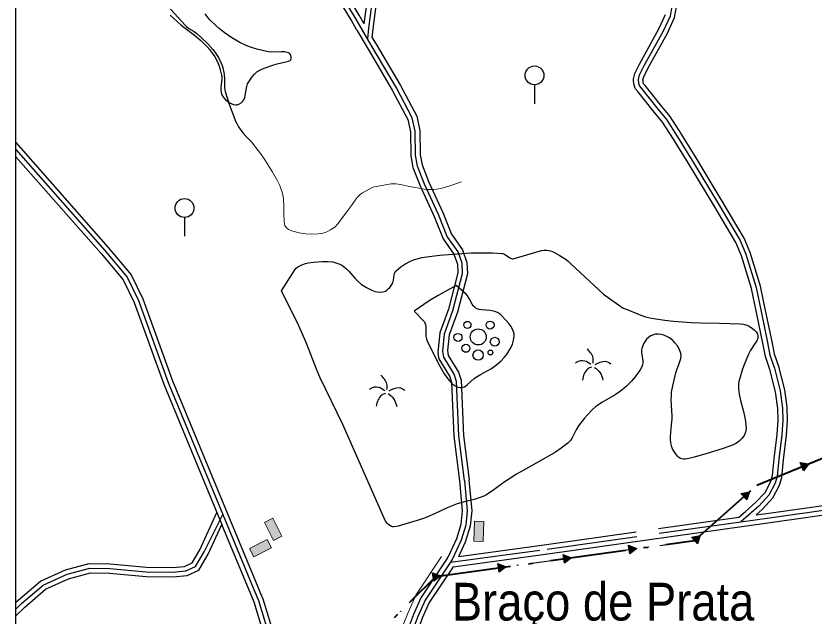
# Model space of a CAD drawing. Extents: x -64005 to -55000, y -89025 to -80000.
# Drawn here: x -64000 to -62306, y -86993 to -85720 of the extents above; entities that cross this region are included whole.
import ezdxf
from ezdxf.enums import TextEntityAlignment as Align

# ---------------------------------------------------------------- set-up
doc = ezdxf.new("R2010")
doc.units = 0
doc.header["$LTSCALE"] = 32
for name, pattern in [('DASH_DOUBLE_DOT', [9.2, 5, -1.2, 0.3, -1.2, 0.3, -1.2]), ('DOT_DASHED', [7.7, 5, -1.2, 0.3, -1.2]), ('LONG_DASHED', [7.5, 6, -1.5])]:
    doc.linetypes.add(name, pattern=pattern)
for name, color, linetype, lineweight in [('18', 7, 'Continuous', 25), ('2', 7, 'Continuous', 25), ('24', 7, 'Continuous', 25), ('32', 7, 'Continuous', 25), ('33', 7, 'Continuous', 25), ('34', 7, 'Continuous', 25), ('39', 7, 'LONG_DASHED', 25), ('6', 7, 'Continuous', 25), ('63', 7, 'DASH_DOUBLE_DOT', 25), ('7', 7, 'Continuous', 13), ('8', 7, 'Continuous', 25)]:
    doc.layers.add(name, color=color, linetype=linetype, lineweight=lineweight)
doc.layers.add('45', color=7, linetype='Continuous')

msp = doc.modelspace()

# ---------------------------------------------------------------- hatches: boundary and pattern name
at = {"layer": '18'}
for points in [[(-62335.55, -86667.32), (-62317.22, -86669.79), (-62328.52, -86684.43)], [(-62461.12, -86732.67), (-62443, -86728.94), (-62448.82, -86746.5)], [(-62565.74, -86825.7), (-62547.62, -86821.96), (-62553.45, -86839.52)], [(-62699.56, -86842.72), (-62682.41, -86849.67), (-62697, -86861.04)], [(-62838.22, -86862.05), (-62821.07, -86869), (-62835.66, -86880.37)], [(-62976.88, -86881.37), (-62959.73, -86888.32), (-62974.32, -86899.7)], [(-63115.54, -86900.7), (-63098.39, -86907.65), (-63112.98, -86919.02)]]:
    msp.add_hatch(color=256, dxfattribs=at).paths.add_polyline_path(points)
at = {"layer": '7'}
for points in [[(-63435.3, -86823.22), (-63454.7, -86785.41), (-63472.5, -86794.54), (-63453.1, -86832.35)], [(-63008.3, -86834.71), (-63006.89, -86792.23), (-63026.88, -86791.57), (-63028.29, -86834.05)], [(-63495.3, -86867.24), (-63457.47, -86847.86), (-63466.58, -86830.06), (-63504.41, -86849.44)]]:
    msp.add_hatch(color=256, dxfattribs=at).paths.add_polyline_path(points)

# ---------------------------------------------------------------- linework, layer by layer
at = {"layer": '18'}
for p, q in [((-62400.47, -86703.99), (-62332.03, -86675.88)), ((-62510.26, -86788.74), (-62454.97, -86739.59)), ((-62632.89, -86842.77), (-62559.62, -86832.55)), ((-62771.55, -86862.09), (-62698.28, -86851.88)), ((-62910.21, -86881.42), (-62836.94, -86871.21)), ((-63048.87, -86900.75), (-62975.6, -86890.54)), ((-63165.4, -86965), (-63112.65, -86913.14))]:
    msp.add_line(p, q, dxfattribs=at)
at = {"layer": '18', "linetype": 'DOT_DASHED', "lineweight": 40}
msp.add_lwpolyline([(-64000, -87327.84), (-63934.19, -87335.68), (-63775.91, -87352.69), (-63696.16, -87339.73), (-63513.74, -87307.46), (-63108.5, -86909.06), (-62559.52, -86832.54), (-62427.35, -86715.03), (-61987.81, -86534.48)], dxfattribs=at)
at = {"layer": '18'}
for points in [[(-62335.55, -86667.32), (-62317.22, -86669.79), (-62328.52, -86684.43)], [(-62461.12, -86732.67), (-62443, -86728.94), (-62448.82, -86746.5)], [(-62565.74, -86825.7), (-62547.62, -86821.96), (-62553.45, -86839.52)], [(-62699.56, -86842.72), (-62682.41, -86849.67), (-62697, -86861.04)], [(-62838.22, -86862.05), (-62821.07, -86869), (-62835.66, -86880.37)], [(-62976.88, -86881.37), (-62959.73, -86888.32), (-62974.32, -86899.7)], [(-63115.54, -86900.7), (-63098.39, -86907.65), (-63112.98, -86919.02)]]:
    msp.add_lwpolyline(points, close=True, dxfattribs=at)
for centre in [(-62423.59, -86713.49), (-62528.94, -86805.35), (-62657.66, -86846.22), (-62796.31, -86865.54), (-62934.97, -86884.87), (-63073.63, -86904.2), (-63183.23, -86982.53)]:
    msp.add_circle(centre, 0.5, dxfattribs=at)
at = {"layer": '2'}
msp.add_lwpolyline([(-63671.62, -85705.77), (-63640.29, -85740), (-63637.94, -85742.29), (-63632.72, -85746.26), (-63621.42, -85753.24), (-63616.07, -85757.12), (-63608.04, -85764.11), (-63592.74, -85778.99), (-63581.84, -85791.28), (-63576.86, -85797.78), (-63569.95, -85808.23), (-63564.84, -85818.32), (-63562.25, -85825.27), (-63560.82, -85829.99), (-63558.56, -85839.62), (-63557.89, -85844.11), (-63557.49, -85853.21), (-63557.58, -85865.4), (-63557.3, -85871.43), (-63556.44, -85877.36), (-63555.71, -85880.28), (-63546.44, -85909.31), (-63537.87, -85933.33), (-63533.71, -85943.11), (-63531.34, -85947.87), (-63527.43, -85954.82), (-63520.76, -85964.81), (-63518.01, -85968.31), (-63512.03, -85974.86), (-63499.54, -85987.41)], dxfattribs=at)
at = {"layer": '2', "lineweight": 13}
msp.add_lwpolyline([(-63054.23, -86071.49), (-63081.28, -86080.78), (-63095.12, -86084.86), (-63102.22, -86086.39), (-63112.96, -86087.88), (-63123.68, -86088.23), (-63128.99, -86087.91), (-63136.9, -86086.86), (-63152.71, -86083.7), (-63164.59, -86081.51), (-63171, -86080.39), (-63183.9, -86077.69), (-63193.59, -86076.17), (-63203.23, -86075.92), (-63208.02, -86076.52), (-63242.68, -86082.95), (-63264.05, -86095.08), (-63268.31, -86097.92), (-63270.91, -86100.1), (-63275.65, -86105.03), (-63279.93, -86110.52), (-63287.84, -86122.23), (-63293.95, -86130.75), (-63316.73, -86160.71), (-63323.42, -86167.62), (-63328.46, -86171.53), (-63332.11, -86173.84), (-63340.1, -86177.83), (-63343.73, -86179.22), (-63351.01, -86181.19), (-63358.29, -86182.3), (-63372.85, -86182.82), (-63384.46, -86182.24), (-63390.27, -86181.57), (-63398.97, -86180.04), (-63412.02, -86176.41), (-63421.28, -86172.67), (-63425.26, -86169.99), (-63428.19, -86166.46), (-63429.11, -86164.29), (-63430.73, -86155.89), (-63431.05, -86139.03), (-63431.05, -86122.46), (-63432.15, -86109.54), (-63433.12, -86103.12), (-63435.24, -86093.61), (-63438.27, -86084.26), (-63440.16, -86079.67), (-63445.1, -86069.38), (-63456.17, -86049.85), (-63471.75, -86024.8), (-63478.85, -86014.39), (-63497.99, -85989.43), (-63499.54, -85987.41)], dxfattribs=at)
at = {"layer": '24'}
for points in [[(-63972.31, -87227.87), (-63975.53, -87229.32), (-64000, -87237.1), (-64000, -85340.91)], [(-63672.91, -85718.52), (-63657.12, -85732.6), (-63648.98, -85739.3), (-63621.27, -85760.7), (-63607.76, -85772.28), (-63594.26, -85785.22), (-63588.51, -85791.69), (-63583.27, -85798.56), (-63577.95, -85806.69), (-63572.33, -85817.04), (-63569.54, -85824.08), (-63567.39, -85831.23), (-63563.97, -85845.71), (-63563.33, -85850.22), (-63563.26, -85853.26), (-63565.14, -85871.86), (-63565.23, -85876.01), (-63564.47, -85882.18), (-63562.71, -85887.27), (-63559.43, -85892.76), (-63554.39, -85898.38), (-63550.55, -85901.52), (-63546.48, -85904.19), (-63538.15, -85908.05), (-63534.01, -85908.71), (-63531.02, -85908.44), (-63526.98, -85907.25), (-63522.26, -85904.55), (-63518.19, -85900.39), (-63516.4, -85897.6), (-63514.28, -85892.69), (-63513.17, -85888.59), (-63510.17, -85869.88), (-63508.17, -85864.12), (-63498.52, -85849.09), (-63493.86, -85843.35), (-63488.39, -85838.36), (-63482.47, -85834.66), (-63476.79, -85831.95), (-63471.04, -85829.66), (-63454.99, -85824.07), (-63445.82, -85821.71), (-63427.32, -85817.57), (-63421.38, -85815.84), (-63417.95, -85814.55), (-63416.38, -85812.69), (-63415.75, -85809.89), (-63415.79, -85807.73), (-63416.85, -85803.29), (-63418.39, -85800.39)], [(-63418.39, -85800.39), (-63419.72, -85798.91), (-63421.65, -85797.82), (-63430.05, -85796.3), (-63436.9, -85796.05), (-63457.57, -85796.57), (-63464.31, -85795.96), (-63467.62, -85795.31), (-63489.04, -85790.05), (-63499.7, -85786.93), (-63510.25, -85783.11), (-63524.68, -85776.36), (-63542.07, -85766.42), (-63558.31, -85755.12), (-63568.65, -85746.76), (-63575.37, -85740.81), (-63588.52, -85727.95), (-63592.16, -85723.99), (-63598.7, -85715.79)], [(-63305.96, -86586.27), (-63354.8, -86486.09), (-63362.27, -86468.84), (-63382.75, -86416.19), (-63393.64, -86390.17), (-63399.67, -86377.43), (-63436.68, -86303.06), (-63408.14, -86258.62), (-63405.08, -86255.2), (-63401.54, -86252.28), (-63397.14, -86249.59), (-63393.31, -86247.8), (-63385.56, -86245.21), (-63378.96, -86243.74), (-63368.76, -86242.28), (-63349.01, -86240.68), (-63338.26, -86240.46), (-63327.37, -86241.68), (-63316.66, -86244.69), (-63312.74, -86246.35), (-63308.29, -86248.72), (-63305.52, -86250.51), (-63297.96, -86256.69), (-63293.38, -86261.33), (-63280.5, -86276.14), (-63273.76, -86283.22), (-63266.25, -86289.45), (-63255.83, -86295.87), (-63244.57, -86301.49), (-63237.65, -86304.01), (-63234.2, -86304.91), (-63227.43, -86305.86), (-63220.94, -86305.42), (-63215.71, -86303.56), (-63212.94, -86301.75), (-63209.05, -86298.25), (-63206.61, -86295.56), (-63202.06, -86289.78), (-63200.14, -86286.33), (-63199.2, -86283.35), (-63198.64, -86280.24), (-63197.46, -86269.21), (-63196.72, -86266.27), (-63195.15, -86262.89), (-63192.89, -86260.22), (-63187, -86255.23), (-63182.97, -86252.15), (-63174.68, -86246.6), (-63162.17, -86240.01), (-63154.18, -86236.8), (-63148.05, -86234.81), (-63138.62, -86232.52), (-63122.74, -86230.1), (-63100.57, -86227.39), (-63063.61, -86224.13), (-63034, -86222.51), (-63012.26, -86222.05), (-62988.07, -86222.49), (-62968.82, -86223.52), (-62966.8, -86223.85), (-62962.92, -86225.48), (-62951.86, -86233.07), (-62948.16, -86234.69), (-62946.26, -86235.02), (-62944.33, -86234.94), (-62884.28, -86217.39), (-62879.04, -86216.39), (-62873.23, -86216.41), (-62868.59, -86217.17), (-62865.12, -86218.11), (-62858.18, -86220.8), (-62846.65, -86226.98), (-62833.88, -86235.06), (-62827.65, -86240.19), (-62822.3, -86245.77), (-62752.81, -86310.19), (-62711.09, -86339.75)], [(-62711.09, -86339.75), (-62702.54, -86342.74), (-62673.52, -86354.61), (-62663.67, -86357.97), (-62651.04, -86361.02), (-62641.69, -86362.57), (-62622.95, -86365.23), (-62604.17, -86367.33), (-62566.49, -86370.17), (-62546.58, -86370.95), (-62506.74, -86371.51), (-62462.76, -86372.82), (-62455.77, -86373.8), (-62448.78, -86375.78), (-62445.29, -86377.28), (-62439.21, -86380.7), (-62436.26, -86382.75), (-62432.18, -86386.14), (-62428.75, -86389.84), (-62425.94, -86394.39), (-62424.94, -86397.72), (-62424.91, -86400.71), (-62425.48, -86403.38), (-62427.59, -86408.72), (-62430.67, -86414.05), (-62441.72, -86430.35), (-62445.29, -86437.4), (-62454.8, -86461.43), (-62459.22, -86473.65), (-62463.03, -86486.09), (-62465.24, -86495.33), (-62466.07, -86501.22), (-62466.36, -86511.1), (-62465.11, -86522.25), (-62462.01, -86535.56), (-62455.57, -86558.75), (-62452.1, -86575.12), (-62450.42, -86586.69), (-62450.32, -86595.34), (-62451.39, -86602.45), (-62452.74, -86606.58), (-62454.94, -86610.91), (-62459.06, -86616.47), (-62463.39, -86620.7), (-62468.25, -86624.4), (-62471.7, -86626.54), (-62478.89, -86629.96), (-62498.48, -86637.04), (-62537.97, -86649.33), (-62560.37, -86655.66), (-62571.58, -86658.51), (-62578.92, -86659.81), (-62582.67, -86659.87), (-62586.38, -86659.34), (-62590.62, -86657.73), (-62593.52, -86655.79), (-62596.03, -86653.41), (-62600.27, -86648.19), (-62604.24, -86641.92), (-62606.28, -86637.73), (-62607.88, -86633.53), (-62609.91, -86625.11), (-62610.63, -86618.08), (-62610.7, -86612.45), (-62610.2, -86603.98), (-62608.22, -86586.99), (-62607.2, -86574.23)], [(-62607.2, -86574.23), (-62607.23, -86567.84), (-62608.94, -86534.51), (-62608.71, -86523.42), (-62608.25, -86517.9), (-62605.97, -86504.14), (-62599.08, -86477.15), (-62597, -86470.33), (-62591.97, -86456.76), (-62588.9, -86446.59), (-62588.28, -86440.32), (-62588.85, -86435.33), (-62591.32, -86427.85), (-62593.93, -86422.89), (-62596.06, -86419.58), (-62601.12, -86412.97), (-62604.15, -86409.65), (-62606.22, -86407.67), (-62612.58, -86402.81), (-62616.97, -86400.34), (-62624.48, -86397.32), (-62630.66, -86395.66), (-62635.78, -86394.93), (-62642.47, -86395.2), (-62646.53, -86396.08), (-62652.47, -86398.56), (-62654.37, -86399.71), (-62657.14, -86401.77), (-62661.21, -86405.68), (-62663.85, -86408.95), (-62666.99, -86414.09), (-62668.67, -86417.67), (-62671.4, -86425.22), (-62672.06, -86428.01), (-62672.28, -86433.76), (-62669.53, -86451.47), (-62669.35, -86455.31), (-62669.9, -86459.95), (-62671.4, -86463.93), (-62675.06, -86470.38), (-62677.67, -86474.53), (-62686.28, -86486.33), (-62692.63, -86493.71), (-62699.41, -86500.72), (-62704.16, -86505.23), (-62714.17, -86513.86), (-62718.62, -86517.29), (-62727.88, -86523.48), (-62756.59, -86539.95), (-62765.73, -86545.93), (-62770.1, -86549.21), (-62776.31, -86554.62), (-62786.83, -86565.61), (-62793.39, -86573.32), (-62805.85, -86589.27), (-62810.86, -86597.45), (-62819.36, -86614.91), (-62822.8, -86620.23), (-62824.8, -86622.66), (-62828.25, -86625.95), (-62842.69, -86636.85), (-62854.65, -86644.88), (-62873.1, -86656.07), (-62929.65, -86687.37), (-62938.91, -86692.81), (-62952.52, -86701.36), (-62963.55, -86709.08), (-62985.3, -86725.15), (-62992.76, -86730.21), (-63002.44, -86736), (-63007.18, -86738.39), (-63016.99, -86742.3), (-63027.14, -86745.38), (-63047.86, -86750.45), (-63063.22, -86754.71), (-63070.67, -86757.41), (-63084.5, -86763.4), (-63111.88, -86776.2), (-63132.81, -86784.93), (-63148.3, -86790.12), (-63188.7, -86801.9), (-63193.26, -86802.92), (-63197.79, -86803.35), (-63200.02, -86803.27), (-63204.45, -86802), (-63209.21, -86798.63), (-63212.02, -86795.59), (-63215.95, -86789.75), (-63218.37, -86784.94), (-63305.96, -86586.27)]]:
    msp.add_lwpolyline(points, dxfattribs=at)
msp.add_lwpolyline([(-63065.82, -86291.3), (-63104.09, -86312.94), (-63122.95, -86324.2), (-63155.01, -86345.83), (-63134.97, -86366.49), (-63133.01, -86368.96), (-63132.03, -86370.74), (-63130.7, -86374.58), (-63129.92, -86380.91), (-63130.07, -86394.65), (-63129.85, -86399.28), (-63128.85, -86404.92), (-63127.71, -86408.16), (-63100.49, -86462.49), (-63092.02, -86477.24), (-63085.72, -86486.64), (-63079.85, -86494), (-63074.47, -86499.44), (-63071.71, -86501.73), (-63067.5, -86504.54), (-63063.19, -86506.57), (-63058.03, -86507.83), (-63054.25, -86507.95), (-63050.79, -86507.46), (-63047.65, -86506.3), (-63045.12, -86504.79), (-63041.3, -86501.79), (-63027.69, -86489.03), (-63024.73, -86486.78), (-63013.68, -86480.05), (-62990.66, -86467.39), (-62979.21, -86459.54), (-62970.09, -86451.47), (-62963.47, -86444.35), (-62958.94, -86438.72), (-62954.84, -86432.9), (-62949.64, -86423.95), (-62946.29, -86416.4), (-62943.6, -86407.41), (-62942.86, -86403), (-62942.55, -86398.67), (-62942.67, -86394.89), (-62943.21, -86391.57), (-62944.97, -86386.08), (-62949.01, -86378.46), (-62953.66, -86372.02), (-62959.14, -86365.67), (-62971.62, -86353.32), (-62975.43, -86350.35), (-62978.12, -86348.81), (-62983.8, -86346.61), (-62989.76, -86345.32), (-62993.83, -86344.81), (-63010.93, -86343.54), (-63016.52, -86342.53), (-63019.15, -86341.75), (-63022.86, -86340.13), (-63026.21, -86337.84), (-63029.17, -86334.77), (-63031.65, -86331.12), (-63037.81, -86319.01), (-63041.48, -86313.43), (-63043.77, -86311.04)], close=True, dxfattribs=at)
at = {"layer": '32'}
for p, q in [((-62899.32, -85866), (-62899.32, -85906)), ((-63642.15, -86147.31), (-63642.15, -86187.31))]:
    msp.add_line(p, q, dxfattribs=at)
for centre in [(-62899.32, -85846), (-63642.15, -86127.31)]:
    msp.add_circle(centre, 20, dxfattribs=at)
at = {"layer": '33'}
for points in [[(-62775.01, -86456.15), (-62775.01, -86445.31), (-62780.35, -86434.17), (-62787.59, -86426.47)], [(-62779.54, -86459.24), (-62792.74, -86451.82), (-62810.52, -86455.22), (-62812.22, -86456.54)], [(-62778.26, -86464.67), (-62785.98, -86468.39), (-62794, -86478.95), (-62797.64, -86492.07)], [(-62772.06, -86465.21), (-62760.12, -86476.83), (-62754.14, -86492.75)], [(-62770.27, -86459.21), (-62749.29, -86452.39), (-62737.19, -86457.65)], [(-63212.58, -86511.99), (-63212.58, -86501.15), (-63217.92, -86490.01), (-63225.16, -86482.31)], [(-63217.11, -86515.08), (-63230.31, -86507.66), (-63248.09, -86511.06), (-63249.79, -86512.38)], [(-63207.84, -86515.05), (-63186.86, -86508.23), (-63174.76, -86513.49)], [(-63215.83, -86520.51), (-63223.55, -86524.23), (-63231.57, -86534.79), (-63235.21, -86547.91)], [(-63209.63, -86521.05), (-63197.69, -86532.67), (-63191.71, -86548.59)]]:
    msp.add_spline(points, degree=3, dxfattribs=at)
at = {"layer": '34'}
for centre, radius in [((-63041.69, -86375.15), 7.5), ((-62993.69, -86375.62), 8.5), ((-63061.71, -86401.66), 8.5), ((-63018.72, -86400.8), 17), ((-62983.56, -86411.04), 9.5), ((-63044.83, -86424.85), 8.5), ((-63018.97, -86439.23), 11), ((-62992.84, -86433.75), 5)]:
    msp.add_circle(centre, radius, dxfattribs=at)
at = {"layer": '39', "linetype": 'Continuous'}
msp.add_line((-63560.89, -86777.29), (-63494.9, -86936.48), dxfattribs=at)
at = {"layer": '39'}
for points in [[(-63253.9, -85768.32), (-63280.08, -85723.39), (-63339.56, -85625.07), (-63389.57, -85575.91), (-63480.62, -85489.18), (-63583.07, -85394.9)], [(-63244.55, -85691.89), (-63251.71, -85746.02), (-63253.9, -85768.32)], [(-62607.87, -85699.34), (-62611.44, -85720.05), (-62626.08, -85752.08), (-62667.76, -85826.92), (-62676.87, -85845.71), (-62679.08, -85854.54), (-62678.53, -85862.27), (-62676.6, -85868.62), (-62672.18, -85873.87), (-62639.33, -85914.73), (-62619.17, -85939.3), (-62595.98, -85976.01), (-62564.79, -86026.26), (-62509.57, -86117.64), (-62462.9, -86196.04), (-62450.76, -86225.31), (-62428.94, -86295.71), (-62418.45, -86346.8), (-62404.93, -86412.23), (-62399.4, -86439.57), (-62390.01, -86466.62), (-62377.86, -86514.94), (-62372.61, -86551.66), (-62372.33, -86577.34), (-62374.54, -86608.26), (-62380.35, -86660.17), (-62383.94, -86696.62), (-62388.36, -86710.98), (-62401.61, -86736.38), (-62422.87, -86759.31), (-62444.68, -86778.63), (-62461.36, -86792.73)], [(-63047.64, -86705.11), (-63059.65, -86610.54), (-63064.82, -86494.96), (-63069.59, -86479.45), (-63091.93, -86443.41), (-63094.05, -86431.26), (-63090.61, -86394.18), (-63072.5, -86345.01), (-63051.88, -86266.13), (-63052.74, -86244.56), (-63061.36, -86220.41), (-63084.63, -86187.65), (-63102.76, -86141.06), (-63132.93, -86076.39), (-63147.58, -86038.44), (-63151.85, -86015.43), (-63152.72, -85964.55), (-63158.75, -85936.09), (-63192.37, -85872.27), (-63244.09, -85785.16), (-63253.9, -85768.32)], [(-62461.36, -86792.73), (-62400.43, -86784.16), (-62105.63, -86742.73), (-61796.63, -86698.55)], [(-63047.64, -86705.11), (-63041.95, -86769.54), (-63045.25, -86799.68), (-63054.9, -86831.71), (-63073.26, -86871.04), (-63077.84, -86878.72)], [(-64000, -86978.32), (-63988.13, -86966.25), (-63942.44, -86927.45), (-63891.57, -86904.17), (-63843.28, -86891.23), (-63801.03, -86892.08), (-63723.44, -86898.97), (-63667.39, -86899.82), (-63639.38, -86897.14), (-63618.68, -86887.65), (-63600.58, -86856.59), (-63560.89, -86777.29)], [(-63077.84, -86878.72), (-62872.34, -86850.53), (-62461.36, -86792.73)], [(-63077.84, -86878.72), (-63131.49, -86959.16), (-63146.78, -86993.57), (-63157.5, -87021.62)]]:
    msp.add_lwpolyline(points, dxfattribs=at)
at = {"layer": '39', "linetype": 'Continuous'}
for points in [[(-64000, -86003.46), (-63811.7, -86217.23), (-63763.78, -86274.14), (-63739.82, -86323.58), (-63676.93, -86497.37), (-63560.89, -86777.29)], [(-63494.9, -86936.48), (-63485.26, -86959.74), (-63458.91, -87046.23)]]:
    msp.add_lwpolyline(points, dxfattribs=at)
at = {"layer": '6'}
for points in [[(-64000, -85988.33), (-63804.12, -86210.69), (-63755.33, -86268.66), (-63730.59, -86319.69), (-63667.6, -86493.75), (-63488.63, -86925.51), (-63480.72, -86944.59)], [(-64000, -86018.58), (-63819.28, -86223.76), (-63772.23, -86279.63), (-63749.05, -86327.48), (-63686.26, -86500.99), (-63573.41, -86773.2), (-63562.96, -86798.41)], [(-63318.01, -87510.1), (-63350.89, -87470.08), (-63375.98, -87426), (-63406.05, -87375.63), (-63423.29, -87341.93), (-63430.55, -87306.47), (-63429.02, -87264.9), (-63428.29, -87233.1), (-63438.17, -87182.82), (-63457.54, -87085.03), (-63494.68, -86963.12), (-63562.96, -86798.41)], [(-63480.72, -86944.59), (-63475.84, -86956.36), (-63451.26, -87037.02)]]:
    msp.add_lwpolyline(points, dxfattribs=at)
at = {"layer": '63', "linetype": 'Continuous', "lineweight": 13}
msp.add_lwpolyline([(-63096.56, -86866.24), (-63151.27, -86948.27), (-63167.58, -86984.98), (-63177.73, -87011.53)], dxfattribs=at)
at = {"layer": '7'}
for points in [[(-63435.3, -86823.22), (-63454.7, -86785.41), (-63472.5, -86794.54), (-63453.1, -86832.35)], [(-63008.3, -86834.71), (-63006.89, -86792.23), (-63026.88, -86791.57), (-63028.29, -86834.05)], [(-63495.3, -86867.24), (-63457.47, -86847.86), (-63466.58, -86830.06), (-63504.41, -86849.44)]]:
    msp.add_lwpolyline(points, close=True, dxfattribs=at)
at = {"layer": '8', "linetype": 'LONG_DASHED'}
for points in [[(-63260.6, -85736.96), (-63271.48, -85718.28), (-63331.65, -85618.82), (-63382.62, -85568.72), (-63473.78, -85481.88), (-63582.03, -85382.29)], [(-63260.6, -85736.96), (-63254.48, -85690.72)], [(-62465.62, -86783.24), (-62451.22, -86771.07), (-62429.87, -86752.15), (-62409.85, -86730.56), (-62397.65, -86707.16), (-62393.79, -86694.64), (-62390.3, -86659.12), (-62384.5, -86607.35), (-62382.33, -86577.04), (-62382.59, -86553.12), (-62382.6, -86552.44), (-62387.69, -86516.87), (-62399.6, -86469.48), (-62409.07, -86442.21), (-62414.73, -86414.23), (-62428.24, -86348.82), (-62438.64, -86298.21), (-62460.17, -86228.71), (-62471.87, -86200.54), (-62518.15, -86122.78), (-62573.32, -86031.49), (-62604.46, -85981.33), (-62627.29, -85945.16), (-62647.09, -85921.03), (-62679.9, -85880.22), (-62685.57, -85873.49), (-62688.42, -85864.1), (-62688.93, -85856.99), (-62689.17, -85853.66), (-62686.32, -85842.28), (-62676.63, -85822.31), (-62635.01, -85747.56), (-62621.07, -85717.07)], [(-63276.18, -85749.95), (-63252.71, -85790.23), (-63201.1, -85877.16), (-63168.24, -85939.52), (-63162.7, -85965.68), (-63161.83, -86016.43), (-63157.24, -86041.18), (-63142.14, -86080.32), (-63111.96, -86145), (-63093.51, -86192.43), (-63070.31, -86225.08), (-63062.67, -86246.49), (-63062.65, -86246.85), (-63061.93, -86265.04), (-63082.05, -86342.02), (-63100.45, -86391.95), (-63104.26, -86433.03), (-63103.62, -86436.22)], [(-63057.58, -86706.19), (-63069.62, -86611.39), (-63074.73, -86497.27), (-63078.77, -86483.62), (-63101.45, -86447.04), (-63103.62, -86436.22)], [(-62428.99, -86778.08), (-62401.82, -86774.26), (-62107.03, -86732.83), (-61811.5, -86690.58)], [(-63083.97, -86869.46), (-63082.11, -86866.35), (-63064.27, -86828.13), (-63055.09, -86797.68), (-63052.05, -86769.87), (-63052, -86769.43), (-63057.58, -86706.19)], [(-64000, -86963.22), (-63947.86, -86918.93), (-63894.97, -86894.73), (-63844.5, -86881.2), (-63800.48, -86882.09), (-63722.92, -86888.98), (-63667.79, -86889.81), (-63642.01, -86887.35), (-63625.73, -86879.88), (-63609.47, -86851.98), (-63573.41, -86773.2)], [(-63059.95, -86866.17), (-62873.71, -86840.62), (-62465.62, -86783.24)], [(-63083.97, -86869.46), (-63140.28, -86954.32), (-63156.03, -86989.75), (-63164.53, -87012.01)]]:
    msp.add_lwpolyline(points, dxfattribs=at)
at = {"layer": '8'}
for points in [[(-63276.18, -85749.95), (-63288.68, -85728.5), (-63347.47, -85631.32), (-63396.52, -85583.11), (-63487.46, -85496.48), (-63594.73, -85397.75)], [(-63243.63, -85766.07), (-63241.77, -85747.16), (-63234.62, -85693.06)], [(-62428.99, -86778.08), (-62415.87, -86766.46), (-62393.37, -86742.2), (-62379.07, -86714.8), (-62374.09, -86698.59), (-62370.39, -86661.22), (-62364.58, -86609.17), (-62362.33, -86577.63), (-62362.62, -86550.89), (-62362.76, -86549.93), (-62368.04, -86513.01), (-62380.42, -86463.76), (-62389.73, -86436.93), (-62395.13, -86410.23), (-62408.66, -86344.78), (-62419.24, -86293.22), (-62441.35, -86221.91), (-62453.94, -86191.54), (-62500.99, -86112.5), (-62556.26, -86021.04), (-62587.5, -85970.7), (-62611.05, -85933.43), (-62631.57, -85908.43), (-62664.46, -85867.52), (-62667.63, -85863.75), (-62668.64, -85860.44), (-62668.85, -85857.45), (-62668.99, -85855.42), (-62667.42, -85849.14), (-62658.89, -85831.54), (-62617.15, -85756.6), (-62601.81, -85723.03), (-62597.91, -85700.43)], [(-63243.63, -85766.07), (-63235.47, -85780.09), (-63183.64, -85867.38), (-63149.26, -85932.66), (-63142.74, -85963.42), (-63141.87, -86014.43), (-63137.92, -86035.7), (-63123.72, -86072.47), (-63093.55, -86137.13), (-63075.76, -86182.86), (-63052.41, -86215.75), (-63042.81, -86242.64), (-63042.8, -86242.91), (-63041.83, -86267.21), (-63062.95, -86348.01), (-63080.77, -86396.41), (-63083.84, -86429.49), (-63083.23, -86433.92), (-63082.41, -86439.79), (-63060.41, -86475.28), (-63054.91, -86492.66), (-63049.68, -86609.69), (-63037.7, -86704.02)], [(-63072.02, -86888.02), (-62870.97, -86860.44), (-62399.04, -86794.06), (-62104.23, -86752.63), (-61709.1, -86696.15)], [(-63059.95, -86866.17), (-63045.53, -86835.28), (-63035.41, -86801.68), (-63031.92, -86769.81), (-63031.9, -86769.65), (-63037.7, -86704.02)], [(-64000, -86992.57), (-63981.32, -86973.58), (-63937.02, -86935.97), (-63888.17, -86913.61), (-63842.06, -86901.26), (-63801.58, -86902.07), (-63723.96, -86908.96), (-63666.99, -86909.83), (-63636.75, -86906.93), (-63611.63, -86895.42), (-63591.69, -86861.2), (-63562.96, -86798.41)], [(-63072.02, -86888.02), (-63122.7, -86964), (-63137.53, -86997.39), (-63143.58, -87013.22)]]:
    msp.add_lwpolyline(points, dxfattribs=at)

# ---------------------------------------------------------------- texts
at = {"layer": '45', "width": 0.9}
msp.add_text('Braço de Prata', height=80, rotation=0.008, dxfattribs=at).set_placement((-62753.69, -87002.19), align=Align.CENTER)

doc.saveas('drawing.dxf')
